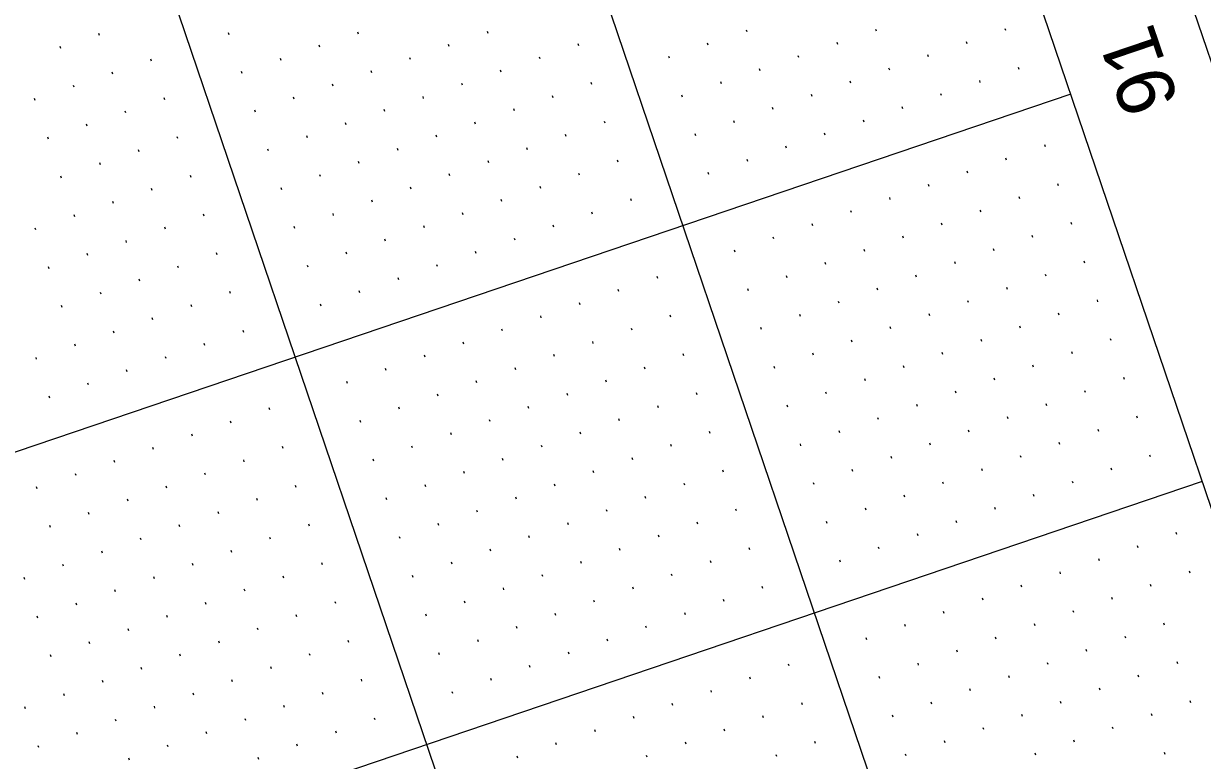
# Model space of a CAD drawing. Extents: x 2150318 to 2152065, y 143281 to 145371.
# Drawn here: x 2151643.3 to 2151787.3, y 144041.7 to 144131.7 of the extents above; entities that cross this region are included whole.
import ezdxf

# ---------------------------------------------------------------- set-up
doc = ezdxf.new("R2010")
doc.units = 0
for name, color, linetype in [('SHT_Plan_Profile_Sheet_Sta_Txt', 7, 'Continuous'), ('SHT_Profile_Grid_Major', 7, 'Continuous'), ('SHT_Profile_Grid_Minor', 7, 'Continuous'), ('SHT_Sheet_Border', 7, 'Continuous')]:
    doc.layers.add(name, color=color, linetype=linetype)

msp = doc.modelspace()

# ---------------------------------------------------------------- linework, layer by layer
at = {"layer": 'SHT_Profile_Grid_Major'}
for p, q in [((2151832.26, 143787.41), (2151326.27, 145278.92)), ((2151784.91, 143771.34), (2151278.93, 145262.85)), ((2151771.19, 144123.08), (2151340.31, 143976.9)), ((2151787.25, 144075.73), (2151356.37, 143929.56))]:
    msp.add_line(p, q, dxfattribs=at)
at = {"layer": 'SHT_Profile_Grid_Minor'}
for p, q in [((2151652.6, 144130.24), (2151652.52, 144130.47)), ((2151668.41, 144130.32), (2151668.33, 144130.56)), ((2151684.22, 144130.4), (2151684.14, 144130.64)), ((2151700.04, 144130.49), (2151699.95, 144130.73)), ((2151731.66, 144130.66), (2151731.58, 144130.89)), ((2151747.47, 144130.74), (2151747.39, 144130.98)), ((2151763.28, 144130.82), (2151763.2, 144131.06)), ((2151647.87, 144128.63), (2151647.79, 144128.87)), ((2151679.49, 144128.8), (2151679.41, 144129.04)), ((2151695.3, 144128.88), (2151695.22, 144129.12)), ((2151711.11, 144128.97), (2151711.03, 144129.2)), ((2151726.92, 144129.05), (2151726.84, 144129.29)), ((2151742.73, 144129.13), (2151742.65, 144129.37)), ((2151758.54, 144129.22), (2151758.46, 144129.46)), ((2151658.94, 144127.11), (2151658.86, 144127.34)), ((2151674.75, 144127.19), (2151674.67, 144127.43)), ((2151690.57, 144127.28), (2151690.49, 144127.51)), ((2151706.38, 144127.36), (2151706.3, 144127.6)), ((2151722.19, 144127.44), (2151722.11, 144127.68)), ((2151738, 144127.53), (2151737.92, 144127.76)), ((2151753.81, 144127.61), (2151753.73, 144127.85)), ((2151685.83, 144125.67), (2151685.75, 144125.91)), ((2151701.64, 144125.75), (2151701.56, 144125.99)), ((2151733.26, 144125.92), (2151733.18, 144126.16)), ((2151749.08, 144126.01), (2151748.99, 144126.24)), ((2151764.89, 144126.09), (2151764.81, 144126.33)), ((2151654.21, 144125.5), (2151654.13, 144125.74)), ((2151670.02, 144125.59), (2151669.94, 144125.82)), ((2151712.72, 144124.23), (2151712.64, 144124.47)), ((2151728.53, 144124.32), (2151728.45, 144124.55)), ((2151744.34, 144124.4), (2151744.26, 144124.64)), ((2151760.15, 144124.48), (2151760.07, 144124.72)), ((2151649.47, 144123.9), (2151649.39, 144124.13)), ((2151681.1, 144124.06), (2151681.02, 144124.3)), ((2151696.91, 144124.15), (2151696.83, 144124.38)), ((2151739.61, 144122.79), (2151739.52, 144123.03)), ((2151755.42, 144122.88), (2151755.34, 144123.11)), ((2151644.74, 144122.29), (2151644.66, 144122.53)), ((2151660.55, 144122.37), (2151660.47, 144122.61)), ((2151676.36, 144122.46), (2151676.28, 144122.69)), ((2151692.17, 144122.54), (2151692.09, 144122.78)), ((2151707.98, 144122.63), (2151707.9, 144122.86)), ((2151723.79, 144122.71), (2151723.71, 144122.95)), ((2151655.81, 144120.77), (2151655.73, 144121)), ((2151671.63, 144120.85), (2151671.55, 144121.09)), ((2151687.44, 144120.93), (2151687.36, 144121.17)), ((2151703.25, 144121.02), (2151703.17, 144121.26)), ((2151734.87, 144121.19), (2151734.79, 144121.42)), ((2151750.68, 144121.27), (2151750.6, 144121.51)), ((2151651.08, 144119.16), (2151651, 144119.4)), ((2151682.7, 144119.33), (2151682.62, 144119.57)), ((2151698.51, 144119.41), (2151698.43, 144119.65)), ((2151714.32, 144119.5), (2151714.24, 144119.73)), ((2151730.14, 144119.58), (2151730.05, 144119.82)), ((2151745.95, 144119.66), (2151745.87, 144119.9)), ((2151646.34, 144117.55), (2151646.26, 144117.79)), ((2151662.16, 144117.64), (2151662.08, 144117.87)), ((2151677.97, 144117.72), (2151677.89, 144117.96)), ((2151693.78, 144117.81), (2151693.7, 144118.04)), ((2151709.59, 144117.89), (2151709.51, 144118.13)), ((2151725.4, 144117.97), (2151725.32, 144118.21)), ((2151741.21, 144118.06), (2151741.13, 144118.29)), ((2151657.42, 144116.03), (2151657.34, 144116.27)), ((2151673.23, 144116.12), (2151673.15, 144116.35)), ((2151689.04, 144116.2), (2151688.96, 144116.44)), ((2151704.85, 144116.28), (2151704.77, 144116.52)), ((2151736.48, 144116.45), (2151736.4, 144116.69)), ((2151768.1, 144116.62), (2151768.02, 144116.86)), ((2151652.69, 144114.43), (2151652.61, 144114.66)), ((2151684.31, 144114.59), (2151684.23, 144114.83)), ((2151700.12, 144114.68), (2151700.04, 144114.91)), ((2151715.93, 144114.76), (2151715.85, 144115)), ((2151731.74, 144114.85), (2151731.66, 144115.08)), ((2151763.36, 144115.01), (2151763.28, 144115.25)), ((2151647.95, 144112.82), (2151647.87, 144113.06)), ((2151663.76, 144112.9), (2151663.68, 144113.14)), ((2151679.57, 144112.99), (2151679.49, 144113.22)), ((2151695.38, 144113.07), (2151695.3, 144113.31)), ((2151711.2, 144113.16), (2151711.12, 144113.39)), ((2151727.01, 144113.24), (2151726.93, 144113.48)), ((2151758.63, 144113.41), (2151758.55, 144113.64)), ((2151659.03, 144111.3), (2151658.95, 144111.53)), ((2151674.84, 144111.38), (2151674.76, 144111.62)), ((2151690.65, 144111.46), (2151690.57, 144111.7)), ((2151706.46, 144111.55), (2151706.38, 144111.79)), ((2151753.89, 144111.8), (2151753.81, 144112.04)), ((2151769.71, 144111.88), (2151769.62, 144112.12)), ((2151685.91, 144109.86), (2151685.83, 144110.1)), ((2151701.73, 144109.94), (2151701.65, 144110.18)), ((2151717.54, 144110.03), (2151717.46, 144110.26)), ((2151749.16, 144110.19), (2151749.08, 144110.43)), ((2151764.97, 144110.28), (2151764.89, 144110.52)), ((2151654.29, 144109.69), (2151654.21, 144109.93)), ((2151712.8, 144108.42), (2151712.72, 144108.66)), ((2151744.42, 144108.59), (2151744.34, 144108.82)), ((2151760.24, 144108.67), (2151760.15, 144108.91)), ((2151649.56, 144108.08), (2151649.48, 144108.32)), ((2151665.37, 144108.17), (2151665.29, 144108.41)), ((2151681.18, 144108.25), (2151681.1, 144108.49)), ((2151696.99, 144108.34), (2151696.91, 144108.57)), ((2151739.69, 144106.98), (2151739.61, 144107.22)), ((2151755.5, 144107.07), (2151755.42, 144107.3)), ((2151771.31, 144107.15), (2151771.23, 144107.39)), ((2151644.82, 144106.48), (2151644.74, 144106.71)), ((2151660.63, 144106.56), (2151660.55, 144106.8)), ((2151676.44, 144106.65), (2151676.36, 144106.88)), ((2151692.26, 144106.73), (2151692.18, 144106.97)), ((2151708.07, 144106.81), (2151707.99, 144107.05)), ((2151766.58, 144105.54), (2151766.5, 144105.78)), ((2151655.9, 144104.96), (2151655.82, 144105.19)), ((2151687.52, 144105.12), (2151687.44, 144105.36)), ((2151703.33, 144105.21), (2151703.25, 144105.44)), ((2151734.95, 144105.38), (2151734.87, 144105.61)), ((2151750.77, 144105.46), (2151750.69, 144105.7)), ((2151651.16, 144103.35), (2151651.08, 144103.59)), ((2151666.97, 144103.43), (2151666.89, 144103.67)), ((2151682.79, 144103.52), (2151682.71, 144103.75)), ((2151698.6, 144103.6), (2151698.52, 144103.84)), ((2151730.22, 144103.77), (2151730.14, 144104.01)), ((2151746.03, 144103.85), (2151745.95, 144104.09)), ((2151761.84, 144103.94), (2151761.76, 144104.17)), ((2151646.43, 144101.74), (2151646.35, 144101.98)), ((2151662.24, 144101.83), (2151662.16, 144102.06)), ((2151678.05, 144101.91), (2151677.97, 144102.15)), ((2151693.86, 144102), (2151693.78, 144102.23)), ((2151741.3, 144102.25), (2151741.22, 144102.48)), ((2151757.11, 144102.33), (2151757.03, 144102.57)), ((2151772.92, 144102.41), (2151772.84, 144102.65)), ((2151657.5, 144100.22), (2151657.42, 144100.46)), ((2151689.13, 144100.39), (2151689.05, 144100.63)), ((2151720.75, 144100.56), (2151720.67, 144100.79)), ((2151736.56, 144100.64), (2151736.48, 144100.88)), ((2151752.37, 144100.72), (2151752.29, 144100.96)), ((2151768.18, 144100.81), (2151768.1, 144101.05)), ((2151652.77, 144098.61), (2151652.69, 144098.85)), ((2151668.58, 144098.7), (2151668.5, 144098.94)), ((2151684.39, 144098.78), (2151684.31, 144099.02)), ((2151716.01, 144098.95), (2151715.93, 144099.19)), ((2151731.83, 144099.03), (2151731.75, 144099.27)), ((2151747.64, 144099.12), (2151747.56, 144099.36)), ((2151763.45, 144099.2), (2151763.37, 144099.44)), ((2151648.03, 144097.01), (2151647.95, 144097.24)), ((2151663.85, 144097.09), (2151663.77, 144097.33)), ((2151679.66, 144097.18), (2151679.58, 144097.41)), ((2151711.28, 144097.34), (2151711.2, 144097.58)), ((2151742.9, 144097.51), (2151742.82, 144097.75)), ((2151758.71, 144097.6), (2151758.63, 144097.83)), ((2151774.52, 144097.68), (2151774.44, 144097.92)), ((2151659.11, 144095.49), (2151659.03, 144095.72)), ((2151706.54, 144095.74), (2151706.46, 144095.97)), ((2151722.36, 144095.82), (2151722.28, 144096.06)), ((2151738.17, 144095.91), (2151738.09, 144096.14)), ((2151753.98, 144095.99), (2151753.9, 144096.23)), ((2151769.79, 144096.07), (2151769.71, 144096.31)), ((2151701.81, 144094.13), (2151701.73, 144094.37)), ((2151717.62, 144094.22), (2151717.54, 144094.45)), ((2151733.43, 144094.3), (2151733.35, 144094.54)), ((2151749.24, 144094.38), (2151749.16, 144094.62)), ((2151765.05, 144094.47), (2151764.97, 144094.7)), ((2151654.38, 144093.88), (2151654.3, 144094.12)), ((2151670.19, 144093.96), (2151670.11, 144094.2)), ((2151712.89, 144092.61), (2151712.81, 144092.85)), ((2151744.51, 144092.78), (2151744.43, 144093.01)), ((2151760.32, 144092.86), (2151760.24, 144093.1)), ((2151776.13, 144092.95), (2151776.05, 144093.18)), ((2151649.64, 144092.27), (2151649.56, 144092.51)), ((2151665.45, 144092.36), (2151665.37, 144092.59)), ((2151697.07, 144092.53), (2151696.99, 144092.76)), ((2151739.77, 144091.17), (2151739.69, 144091.41)), ((2151755.58, 144091.25), (2151755.5, 144091.49)), ((2151771.4, 144091.34), (2151771.32, 144091.58)), ((2151644.91, 144090.67), (2151644.83, 144090.9)), ((2151660.72, 144090.75), (2151660.64, 144090.99)), ((2151692.34, 144090.92), (2151692.26, 144091.16)), ((2151708.15, 144091), (2151708.07, 144091.24)), ((2151723.96, 144091.09), (2151723.88, 144091.32)), ((2151766.66, 144089.73), (2151766.58, 144089.97)), ((2151655.98, 144089.14), (2151655.9, 144089.38)), ((2151687.6, 144089.31), (2151687.52, 144089.55)), ((2151703.42, 144089.4), (2151703.34, 144089.63)), ((2151719.23, 144089.48), (2151719.15, 144089.72)), ((2151735.04, 144089.56), (2151734.96, 144089.8)), ((2151750.85, 144089.65), (2151750.77, 144089.89)), ((2151651.25, 144087.54), (2151651.17, 144087.77)), ((2151682.87, 144087.71), (2151682.79, 144087.94)), ((2151698.68, 144087.79), (2151698.6, 144088.03)), ((2151714.49, 144087.87), (2151714.41, 144088.11)), ((2151746.11, 144088.04), (2151746.03, 144088.28)), ((2151761.93, 144088.13), (2151761.85, 144088.36)), ((2151777.74, 144088.21), (2151777.66, 144088.45)), ((2151646.51, 144085.93), (2151646.43, 144086.17)), ((2151693.95, 144086.18), (2151693.87, 144086.42)), ((2151709.76, 144086.27), (2151709.68, 144086.5)), ((2151725.57, 144086.35), (2151725.49, 144086.59)), ((2151741.38, 144086.44), (2151741.3, 144086.67)), ((2151757.19, 144086.52), (2151757.11, 144086.76)), ((2151773, 144086.6), (2151772.92, 144086.84)), ((2151673.4, 144084.49), (2151673.32, 144084.73)), ((2151689.21, 144084.58), (2151689.13, 144084.81)), ((2151705.02, 144084.66), (2151704.94, 144084.9)), ((2151720.83, 144084.75), (2151720.75, 144084.98)), ((2151736.64, 144084.83), (2151736.56, 144085.07)), ((2151752.46, 144084.91), (2151752.38, 144085.15)), ((2151768.27, 144085), (2151768.19, 144085.23)), ((2151668.66, 144082.89), (2151668.58, 144083.12)), ((2151684.48, 144082.97), (2151684.4, 144083.21)), ((2151700.29, 144083.06), (2151700.21, 144083.29)), ((2151716.1, 144083.14), (2151716.02, 144083.38)), ((2151747.72, 144083.31), (2151747.64, 144083.54)), ((2151763.53, 144083.39), (2151763.45, 144083.63)), ((2151779.34, 144083.48), (2151779.26, 144083.71)), ((2151663.93, 144081.28), (2151663.85, 144081.52)), ((2151695.55, 144081.45), (2151695.47, 144081.69)), ((2151711.36, 144081.53), (2151711.28, 144081.77)), ((2151727.17, 144081.62), (2151727.09, 144081.85)), ((2151742.99, 144081.7), (2151742.91, 144081.94)), ((2151758.8, 144081.78), (2151758.72, 144082.02)), ((2151774.61, 144081.87), (2151774.53, 144082.11)), ((2151659.19, 144079.67), (2151659.11, 144079.91)), ((2151675.01, 144079.76), (2151674.93, 144080)), ((2151690.82, 144079.84), (2151690.74, 144080.08)), ((2151706.63, 144079.93), (2151706.55, 144080.16)), ((2151722.44, 144080.01), (2151722.36, 144080.25)), ((2151738.25, 144080.09), (2151738.17, 144080.33)), ((2151754.06, 144080.18), (2151753.98, 144080.42)), ((2151769.87, 144080.26), (2151769.79, 144080.5)), ((2151670.27, 144078.15), (2151670.19, 144078.39)), ((2151686.08, 144078.24), (2151686, 144078.47)), ((2151701.89, 144078.32), (2151701.81, 144078.56)), ((2151717.7, 144078.4), (2151717.62, 144078.64)), ((2151749.33, 144078.57), (2151749.25, 144078.81)), ((2151765.14, 144078.66), (2151765.06, 144078.89)), ((2151780.95, 144078.74), (2151780.87, 144078.98)), ((2151654.46, 144078.07), (2151654.38, 144078.3)), ((2151697.16, 144076.71), (2151697.08, 144076.95)), ((2151712.97, 144076.8), (2151712.89, 144077.03)), ((2151728.78, 144076.88), (2151728.7, 144077.12)), ((2151744.59, 144076.97), (2151744.51, 144077.2)), ((2151760.4, 144077.05), (2151760.32, 144077.29)), ((2151776.21, 144077.13), (2151776.13, 144077.37)), ((2151649.73, 144076.46), (2151649.64, 144076.7)), ((2151665.54, 144076.55), (2151665.46, 144076.78)), ((2151724.05, 144075.28), (2151723.97, 144075.51)), ((2151739.86, 144075.36), (2151739.78, 144075.6)), ((2151755.67, 144075.44), (2151755.59, 144075.68)), ((2151771.48, 144075.53), (2151771.4, 144075.76)), ((2151644.99, 144074.86), (2151644.91, 144075.09)), ((2151660.8, 144074.94), (2151660.72, 144075.18)), ((2151676.61, 144075.02), (2151676.53, 144075.26)), ((2151692.42, 144075.11), (2151692.34, 144075.34)), ((2151708.23, 144075.19), (2151708.15, 144075.43)), ((2151750.93, 144073.84), (2151750.85, 144074.07)), ((2151766.74, 144073.92), (2151766.66, 144074.16)), ((2151656.07, 144073.33), (2151655.99, 144073.57)), ((2151671.88, 144073.42), (2151671.8, 144073.65)), ((2151687.69, 144073.5), (2151687.61, 144073.74)), ((2151703.5, 144073.59), (2151703.42, 144073.82)), ((2151719.31, 144073.67), (2151719.23, 144073.91)), ((2151651.33, 144071.73), (2151651.25, 144071.96)), ((2151667.14, 144071.81), (2151667.06, 144072.05)), ((2151698.76, 144071.98), (2151698.68, 144072.22)), ((2151714.58, 144072.06), (2151714.5, 144072.3)), ((2151730.39, 144072.15), (2151730.31, 144072.38)), ((2151746.2, 144072.23), (2151746.12, 144072.47)), ((2151762.01, 144072.32), (2151761.93, 144072.55)), ((2151646.6, 144070.12), (2151646.52, 144070.36)), ((2151662.41, 144070.2), (2151662.33, 144070.44)), ((2151678.22, 144070.29), (2151678.14, 144070.53)), ((2151694.03, 144070.37), (2151693.95, 144070.61)), ((2151709.84, 144070.46), (2151709.76, 144070.69)), ((2151725.65, 144070.54), (2151725.57, 144070.78)), ((2151741.46, 144070.62), (2151741.38, 144070.86)), ((2151757.27, 144070.71), (2151757.19, 144070.95)), ((2151657.67, 144068.6), (2151657.59, 144068.84)), ((2151673.48, 144068.68), (2151673.4, 144068.92)), ((2151689.3, 144068.77), (2151689.21, 144069)), ((2151705.11, 144068.85), (2151705.03, 144069.09)), ((2151720.92, 144068.93), (2151720.84, 144069.17)), ((2151752.54, 144069.1), (2151752.46, 144069.34)), ((2151784.16, 144069.27), (2151784.08, 144069.51)), ((2151652.94, 144066.99), (2151652.86, 144067.23)), ((2151668.75, 144067.08), (2151668.67, 144067.31)), ((2151700.37, 144067.24), (2151700.29, 144067.48)), ((2151716.18, 144067.33), (2151716.1, 144067.56)), ((2151731.99, 144067.41), (2151731.91, 144067.65)), ((2151747.8, 144067.5), (2151747.72, 144067.73)), ((2151779.43, 144067.66), (2151779.35, 144067.9)), ((2151648.2, 144065.39), (2151648.12, 144065.62)), ((2151664.01, 144065.47), (2151663.93, 144065.71)), ((2151679.83, 144065.55), (2151679.74, 144065.79)), ((2151695.64, 144065.64), (2151695.56, 144065.87)), ((2151711.45, 144065.72), (2151711.37, 144065.96)), ((2151727.26, 144065.81), (2151727.18, 144066.04)), ((2151743.07, 144065.89), (2151742.99, 144066.13)), ((2151774.69, 144066.06), (2151774.61, 144066.29)), ((2151643.47, 144063.78), (2151643.39, 144064.02)), ((2151659.28, 144063.86), (2151659.2, 144064.1)), ((2151675.09, 144063.95), (2151675.01, 144064.18)), ((2151690.9, 144064.03), (2151690.82, 144064.27)), ((2151706.71, 144064.12), (2151706.63, 144064.35)), ((2151722.52, 144064.2), (2151722.44, 144064.44)), ((2151769.96, 144064.45), (2151769.88, 144064.69)), ((2151785.77, 144064.54), (2151785.69, 144064.77)), ((2151670.36, 144062.34), (2151670.27, 144062.58)), ((2151701.98, 144062.51), (2151701.9, 144062.75)), ((2151717.79, 144062.59), (2151717.71, 144062.83)), ((2151733.6, 144062.68), (2151733.52, 144062.91)), ((2151765.22, 144062.85), (2151765.14, 144063.08)), ((2151781.03, 144062.93), (2151780.95, 144063.17)), ((2151654.54, 144062.26), (2151654.46, 144062.49)), ((2151697.24, 144060.9), (2151697.16, 144061.14)), ((2151713.05, 144060.99), (2151712.97, 144061.22)), ((2151728.86, 144061.07), (2151728.78, 144061.31)), ((2151760.49, 144061.24), (2151760.41, 144061.48)), ((2151776.3, 144061.32), (2151776.22, 144061.56)), ((2151649.81, 144060.65), (2151649.73, 144060.89)), ((2151665.62, 144060.73), (2151665.54, 144060.97)), ((2151681.43, 144060.82), (2151681.35, 144061.06)), ((2151724.13, 144059.46), (2151724.05, 144059.7)), ((2151755.75, 144059.63), (2151755.67, 144059.87)), ((2151771.56, 144059.72), (2151771.48, 144059.95)), ((2151645.07, 144059.04), (2151644.99, 144059.28)), ((2151660.89, 144059.13), (2151660.8, 144059.37)), ((2151676.7, 144059.21), (2151676.62, 144059.45)), ((2151692.51, 144059.3), (2151692.43, 144059.53)), ((2151708.32, 144059.38), (2151708.24, 144059.62)), ((2151751.02, 144058.03), (2151750.94, 144058.26)), ((2151766.83, 144058.11), (2151766.75, 144058.35)), ((2151782.64, 144058.19), (2151782.56, 144058.43)), ((2151656.15, 144057.52), (2151656.07, 144057.76)), ((2151671.96, 144057.61), (2151671.88, 144057.84)), ((2151703.58, 144057.77), (2151703.5, 144058.01)), ((2151719.39, 144057.86), (2151719.31, 144058.09)), ((2151777.9, 144056.59), (2151777.82, 144056.82)), ((2151651.42, 144055.92), (2151651.34, 144056.15)), ((2151667.23, 144056), (2151667.15, 144056.24)), ((2151683.04, 144056.08), (2151682.96, 144056.32)), ((2151698.85, 144056.17), (2151698.77, 144056.4)), ((2151714.66, 144056.25), (2151714.58, 144056.49)), ((2151746.28, 144056.42), (2151746.2, 144056.66)), ((2151762.09, 144056.5), (2151762.01, 144056.74)), ((2151646.68, 144054.31), (2151646.6, 144054.55)), ((2151662.49, 144054.39), (2151662.41, 144054.63)), ((2151678.3, 144054.48), (2151678.22, 144054.71)), ((2151694.11, 144054.56), (2151694.03, 144054.8)), ((2151709.93, 144054.65), (2151709.84, 144054.88)), ((2151757.36, 144054.9), (2151757.28, 144055.13)), ((2151773.17, 144054.98), (2151773.09, 144055.22)), ((2151657.76, 144052.79), (2151657.68, 144053.02)), ((2151673.57, 144052.87), (2151673.49, 144053.11)), ((2151705.19, 144053.04), (2151705.11, 144053.28)), ((2151736.81, 144053.21), (2151736.73, 144053.44)), ((2151752.62, 144053.29), (2151752.54, 144053.53)), ((2151768.43, 144053.38), (2151768.35, 144053.61)), ((2151784.25, 144053.46), (2151784.17, 144053.7)), ((2151653.02, 144051.18), (2151652.94, 144051.42)), ((2151668.83, 144051.26), (2151668.75, 144051.5)), ((2151684.64, 144051.35), (2151684.56, 144051.59)), ((2151700.46, 144051.43), (2151700.37, 144051.67)), ((2151732.08, 144051.6), (2151732, 144051.84)), ((2151747.89, 144051.68), (2151747.81, 144051.92)), ((2151763.7, 144051.77), (2151763.62, 144052.01)), ((2151779.51, 144051.85), (2151779.43, 144052.09)), ((2151648.29, 144049.57), (2151648.21, 144049.81)), ((2151664.1, 144049.66), (2151664.02, 144049.9)), ((2151679.91, 144049.74), (2151679.83, 144049.98)), ((2151695.72, 144049.83), (2151695.64, 144050.06)), ((2151727.34, 144049.99), (2151727.26, 144050.23)), ((2151758.96, 144050.16), (2151758.88, 144050.4)), ((2151774.78, 144050.25), (2151774.7, 144050.48)), ((2151643.55, 144047.97), (2151643.47, 144048.21)), ((2151659.36, 144048.05), (2151659.28, 144048.29)), ((2151675.17, 144048.14), (2151675.09, 144048.37)), ((2151722.61, 144048.39), (2151722.53, 144048.62)), ((2151738.42, 144048.47), (2151738.34, 144048.71)), ((2151754.23, 144048.56), (2151754.15, 144048.79)), ((2151770.04, 144048.64), (2151769.96, 144048.88)), ((2151785.85, 144048.72), (2151785.77, 144048.96)), ((2151670.44, 144046.53), (2151670.36, 144046.77)), ((2151686.25, 144046.61), (2151686.17, 144046.85)), ((2151717.87, 144046.78), (2151717.79, 144047.02)), ((2151733.68, 144046.87), (2151733.6, 144047.1)), ((2151749.5, 144046.95), (2151749.41, 144047.19)), ((2151765.31, 144047.03), (2151765.23, 144047.27)), ((2151781.12, 144047.12), (2151781.04, 144047.35)), ((2151654.63, 144046.45), (2151654.55, 144046.68)), ((2151713.14, 144045.18), (2151713.06, 144045.41)), ((2151728.95, 144045.26), (2151728.87, 144045.5)), ((2151760.57, 144045.43), (2151760.49, 144045.66)), ((2151776.38, 144045.51), (2151776.3, 144045.75)), ((2151649.89, 144044.84), (2151649.81, 144045.08)), ((2151665.7, 144044.92), (2151665.62, 144045.16)), ((2151681.52, 144045.01), (2151681.44, 144045.24)), ((2151724.21, 144043.65), (2151724.13, 144043.89)), ((2151740.03, 144043.74), (2151739.94, 144043.97)), ((2151755.84, 144043.82), (2151755.76, 144044.06)), ((2151771.65, 144043.91), (2151771.57, 144044.14)), ((2151645.16, 144043.23), (2151645.08, 144043.47)), ((2151660.97, 144043.32), (2151660.89, 144043.55)), ((2151676.78, 144043.4), (2151676.7, 144043.64)), ((2151708.4, 144043.57), (2151708.32, 144043.81)), ((2151751.1, 144042.21), (2151751.02, 144042.45)), ((2151766.91, 144042.3), (2151766.83, 144042.54)), ((2151782.72, 144042.38), (2151782.64, 144042.62)), ((2151656.23, 144041.71), (2151656.15, 144041.95)), ((2151672.05, 144041.8), (2151671.97, 144042.03)), ((2151703.67, 144041.96), (2151703.59, 144042.2)), ((2151719.48, 144042.05), (2151719.4, 144042.28)), ((2151735.29, 144042.13), (2151735.21, 144042.37))]:
    msp.add_line(p, q, dxfattribs=at)
at = {"layer": 'SHT_Sheet_Border'}
msp.add_line((2151879.61, 143803.47), (2151457.96, 145046.39), dxfattribs=at)
msp.add_lwpolyline([(2150901.85, 143471.77), (2150395.86, 144963.28), (2151390.2, 145300.6), (2151896.19, 143809.09)], close=True, dxfattribs=at)

# ---------------------------------------------------------------- texts
at = {"layer": 'SHT_Plan_Profile_Sheet_Sta_Txt'}
msp.add_text('91', height=7, rotation=108.7393, dxfattribs=at).set_placement((2151784.45, 144122.1))

doc.saveas('drawing.dxf')
